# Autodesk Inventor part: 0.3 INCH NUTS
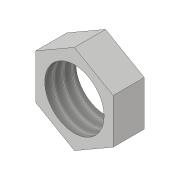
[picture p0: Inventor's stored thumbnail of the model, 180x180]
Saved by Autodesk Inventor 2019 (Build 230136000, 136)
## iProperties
Created: 2019-10
Part Number: 0.3 INCH NUTS
Material: Generic
Document SubType Name: Modeling
Designer: hp
Density: 1 g/cm^3
Appearance: Default
Author: hp
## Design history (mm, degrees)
sketch "Sketch1"
  geometry: L1 (0, 5.732)-(4.964, 2.866); L2 (4.964, 2.866)-(4.964, -2.866); L3 (4.964, -2.866)-(0, -5.732); L4 (0, -5.732)-(-4.964, -2.866); L5 (-4.964, -2.866)-(-4.964, 2.866); L6 (-4.964, 2.866)-(0, 5.732); C1 r 3.81 at (0, 0); 2 further points
  constraints: 12 end point, 2 coincident, 1 centre point, 13 other
  dimensions: "d0" = 7.62 diameter of C1
extrude "Extrusion1" new body sketch "Sketch1" distance "d1" = 4; taper "d2" = 0 deg
thread "Thread1" dims "d3" = 10, "d4" = 0
body "Solid1"
